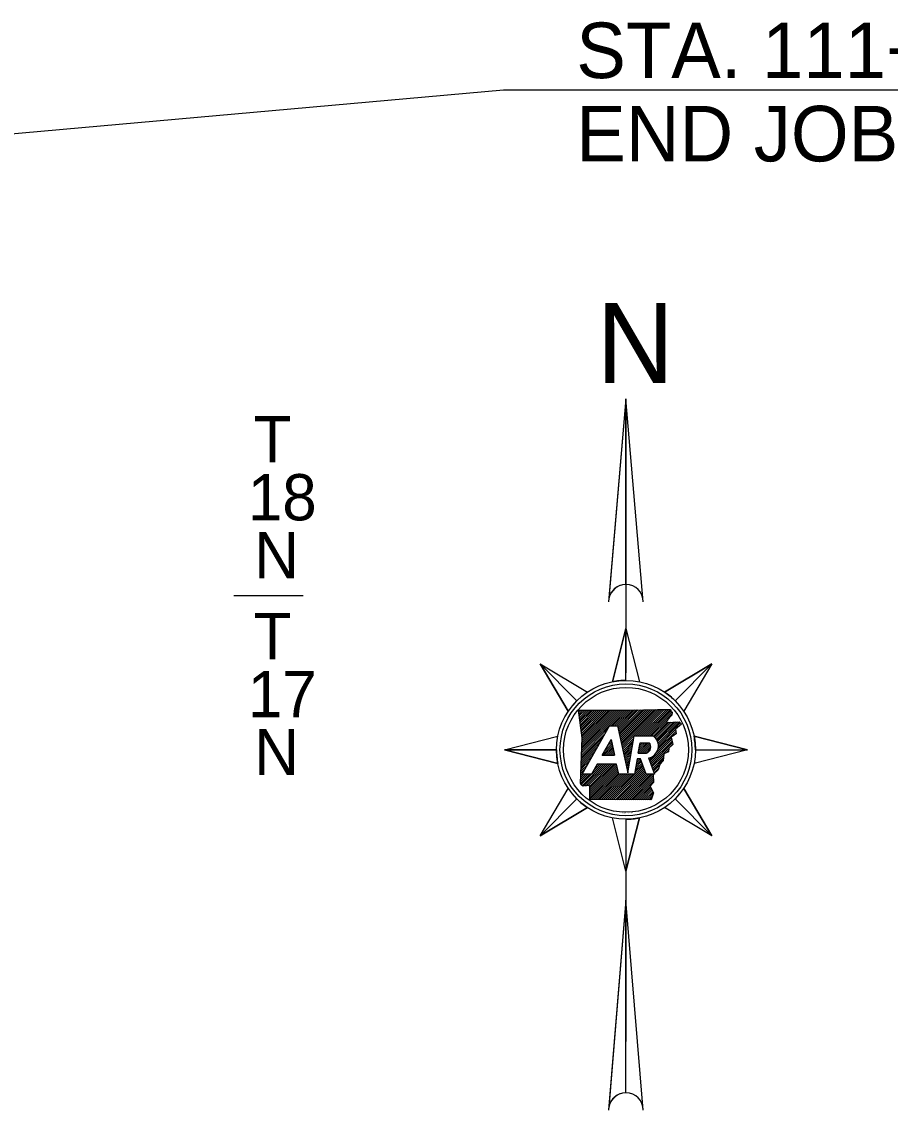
# Model space of a CAD drawing. Extents: x 166 to 3406, y 71 to 2074.
# Drawn here: x 2315.6 to 2690.8, y 490.1 to 960.6 of the extents above; entities that cross this region are included whole.
import ezdxf

# ---------------------------------------------------------------- set-up
doc = ezdxf.new("R2010")
doc.units = 0
for name, color, linetype in [('2', 7, 'Continuous'), ('Default', 7, 'Continuous'), ('Level 6', 7, 'Continuous'), ('R_Draft', 7, 'Continuous')]:
    doc.layers.add(name, color=color, linetype=linetype)

msp = doc.modelspace()

# ---------------------------------------------------------------- linework, layer by layer
at = {"layer": 'Default'}
msp.add_line((2826.89, 931.07), (2523.75, 931.07), dxfattribs=at)
msp.add_lwpolyline([(2523.75, 931.07), (1751.41, 862.02), (1897.01, 884.67), (1902.22, 875.51)], dxfattribs=at)
at = {"layer": 'Level 6'}
msp.add_line((2407.22, 712.51), (2437.22, 712.51), dxfattribs=at)
at = {"layer": 'R_Draft'}
for p, q in [((2576.6, 797.56), (2569.21, 711.09)), ((2576.6, 797.56), (2576.6, 679.13)), ((2576.6, 717.31), (2576.6, 797.56)), ((2569.31, 712.29), (2569.65, 712.63)), ((2569.35, 712.76), (2570.03, 713.44)), ((2576.6, 698.35), (2570.76, 675.28)), ((2576.6, 675.85), (2576.6, 698.35)), ((2539.48, 682.98), (2555.39, 667.07)), ((2555.39, 667.07), (2539.48, 682.98)), ((2539.48, 682.98), (2551.66, 662.53)), ((2613.72, 682.98), (2593.27, 670.79)), ((2597.81, 667.07), (2613.72, 682.98)), ((2597.81, 667.07), (2613.72, 682.98)), ((2556.15, 662.76), (2556.41, 663.03)), ((2556.24, 662.01), (2557.26, 663.03)), ((2556.34, 661.25), (2558.11, 663.03)), ((2556.43, 660.5), (2558.96, 663.03)), ((2556.53, 659.74), (2559.81, 663.03)), ((2556.62, 658.99), (2560.65, 663.02)), ((2556.71, 658.24), (2561.5, 663.02)), ((2556.81, 657.48), (2562.35, 663.02)), ((2556.9, 656.73), (2563.2, 663.02)), ((2557, 655.97), (2564.05, 663.02)), ((2557.09, 655.22), (2564.89, 663.02)), ((2557.18, 654.46), (2565.74, 663.02)), ((2557.28, 653.71), (2566.59, 663.02)), ((2557.37, 652.95), (2567.44, 663.02)), ((2557.4, 644.5), (2575.94, 663.04)), ((2557.43, 645.37), (2575.09, 663.04)), ((2557.46, 646.25), (2574.24, 663.03)), ((2557.47, 652.2), (2568.29, 663.02)), ((2557.49, 647.13), (2573.39, 663.03)), ((2557.52, 648.01), (2572.54, 663.03)), ((2557.55, 648.88), (2571.69, 663.03)), ((2557.56, 651.44), (2569.14, 663.02)), ((2557.57, 649.76), (2570.84, 663.03)), ((2557.6, 650.64), (2569.99, 663.03)), ((2570, 656.25), (2576.79, 663.04)), ((2570.85, 656.25), (2577.64, 663.04)), ((2571.7, 656.25), (2578.5, 663.05)), ((2572.55, 656.25), (2579.36, 663.06)), ((2573.07, 655.93), (2580.22, 663.08)), ((2573.22, 655.23), (2581.08, 663.09)), ((2573.37, 654.53), (2581.94, 663.1)), ((2573.52, 653.83), (2582.81, 663.12)), ((2573.67, 653.13), (2583.67, 663.13)), ((2573.82, 652.43), (2584.53, 663.14)), ((2573.97, 651.74), (2585.39, 663.16)), ((2574.12, 651.04), (2586.25, 663.17)), ((2574.27, 650.34), (2587.12, 663.18)), ((2574.42, 649.64), (2587.98, 663.2)), ((2574.57, 648.94), (2588.84, 663.21)), ((2574.72, 648.24), (2589.7, 663.22)), ((2574.87, 647.54), (2590.57, 663.24)), ((2575.02, 646.84), (2591.44, 663.26)), ((2580.91, 651.89), (2592.3, 663.28)), ((2581.76, 651.89), (2593.17, 663.3)), ((2582.61, 651.89), (2594.04, 663.32)), ((2583.46, 651.89), (2594.91, 663.34)), ((2584.31, 651.89), (2595.78, 663.36)), ((2585.16, 651.89), (2595.97, 662.7)), ((2586, 651.89), (2596.38, 662.26)), ((2586.85, 651.89), (2596.49, 661.52)), ((2587.7, 651.89), (2594.55, 658.74)), ((2557.37, 643.62), (2568.82, 655.07)), ((2557.65, 635.35), (2569.49, 656.25)), ((2569.49, 656.25), (2573.01, 656.25)), ((2588.47, 651.81), (2594.38, 657.72)), ((2588.94, 651.43), (2595.28, 657.77)), ((2589.35, 650.99), (2596.17, 657.81)), ((2589.72, 650.51), (2597.07, 657.86)), ((2590.03, 649.98), (2597.96, 657.91)), ((2590.29, 649.39), (2598.86, 657.95)), ((2590.49, 648.73), (2599.66, 657.91)), ((2590.6, 648), (2600.06, 657.46)), ((2590.61, 647.16), (2598.03, 654.58)), ((2599.68, 656.23), (2600.45, 657)), ((2557.31, 641.86), (2566.61, 651.16)), ((2557.34, 642.74), (2567.71, 653.11)), ((2566.36, 643.55), (2570.23, 650.39)), ((2568.52, 647.37), (2570.46, 649.31)), ((2569.63, 649.32), (2570.31, 650.01)), ((2575.17, 646.14), (2579.98, 650.96)), ((2575.32, 645.44), (2579.8, 649.93)), ((2580.15, 651.89), (2588.37, 651.89)), ((2586.93, 640.93), (2596.33, 650.34)), ((2587.15, 640.31), (2596.49, 649.65)), ((2589.69, 644.54), (2596.17, 651.03)), ((2590.43, 646.13), (2598.13, 653.83)), ((2597.18, 652.03), (2598.23, 653.08)), ((2629.1, 645.85), (2606.02, 651.7)), ((2524.1, 645.85), (2546.6, 645.85)), ((2546.6, 645.85), (2524.1, 645.85)), ((2524.1, 645.85), (2547.17, 640.01)), ((2557.23, 639.23), (2563.28, 645.29)), ((2557.25, 640.11), (2564.39, 647.24)), ((2557.28, 640.99), (2565.5, 649.2)), ((2566.4, 643.55), (2570.76, 647.91)), ((2567.25, 643.55), (2570.91, 647.21)), ((2567.41, 645.41), (2570.61, 648.61)), ((2568.1, 643.55), (2571.06, 646.51)), ((2568.95, 643.55), (2571.21, 645.81)), ((2569.79, 643.55), (2571.36, 645.11)), ((2575.47, 644.75), (2579.63, 648.9)), ((2575.62, 644.05), (2579.45, 647.88)), ((2575.77, 643.35), (2579.27, 646.85)), ((2575.92, 642.65), (2579.09, 645.82)), ((2576.07, 641.95), (2578.91, 644.79)), ((2581.93, 644.47), (2586.4, 648.94)), ((2582.11, 645.5), (2585.55, 648.94)), ((2582.29, 646.52), (2584.7, 648.94)), ((2582.47, 647.55), (2583.85, 648.94)), ((2582.65, 648.58), (2583, 648.94)), ((2582.71, 648.94), (2586.57, 648.94)), ((2582.78, 644.47), (2586.87, 648.56)), ((2583.63, 644.47), (2587.16, 648)), ((2584.48, 644.47), (2587.31, 647.31)), ((2585.33, 644.47), (2587.24, 646.39)), ((2587.38, 639.69), (2596.65, 648.96)), ((2587.61, 639.07), (2596.81, 648.27)), ((2593.91, 644.52), (2595.1, 645.71)), ((2606.6, 645.85), (2629.1, 645.85)), ((2606.6, 645.85), (2629.1, 645.85)), ((2557.17, 637.48), (2561.07, 641.38)), ((2557.2, 638.35), (2562.17, 643.33)), ((2566.36, 643.55), (2571.69, 643.55)), ((2570.64, 643.55), (2571.51, 644.42)), ((2571.49, 643.55), (2571.66, 643.72)), ((2576.22, 641.25), (2578.73, 643.77)), ((2576.37, 640.55), (2578.55, 642.74)), ((2576.51, 639.85), (2578.37, 641.71)), ((2576.66, 639.15), (2578.19, 640.68)), ((2580.66, 637.21), (2583.6, 640.15)), ((2580.84, 638.24), (2583.37, 640.77)), ((2581.02, 639.27), (2583.14, 641.39)), ((2581.2, 640.3), (2582.9, 641.99)), ((2581.38, 641.32), (2582.05, 641.99)), ((2582.92, 641.99), (2581.5, 641.99)), ((2581.93, 644.47), (2585.46, 644.47)), ((2585.38, 635.35), (2582.92, 641.99)), ((2586.4, 642.35), (2588.99, 635.35)), ((2586.47, 642.17), (2586.73, 642.43)), ((2586.7, 641.55), (2588.31, 643.16)), ((2587.84, 638.45), (2592.93, 643.54)), ((2588.07, 637.83), (2592.84, 642.6)), ((2588.3, 637.21), (2592.74, 641.65)), ((2556.98, 631.35), (2560.98, 635.35)), ((2556.99, 632.21), (2560.13, 635.35)), ((2557.02, 633.09), (2559.28, 635.35)), ((2557.05, 633.97), (2558.43, 635.35)), ((2557.08, 634.84), (2557.74, 635.51)), ((2557.11, 635.72), (2558.85, 637.46)), ((2557.14, 636.6), (2559.96, 639.42)), ((2557.29, 630.81), (2566.21, 639.73)), ((2561.71, 635.35), (2557.65, 635.35)), ((2557.8, 630.47), (2567.06, 639.73)), ((2558.41, 630.23), (2567.91, 639.73)), ((2559.41, 630.39), (2568.76, 639.73)), ((2560.28, 630.4), (2569.6, 639.73)), ((2560.94, 630.22), (2570.45, 639.73)), ((2560.97, 628.55), (2572.15, 639.73)), ((2560.97, 629.4), (2571.3, 639.73)), ((2560.97, 627.71), (2572.6, 639.33)), ((2560.98, 626.86), (2572.75, 638.63)), ((2560.98, 626.01), (2572.9, 637.93)), ((2560.98, 625.17), (2573.05, 637.23)), ((2560.99, 624.33), (2573.2, 636.53)), ((2564.2, 639.73), (2561.71, 635.35)), ((2561.84, 624.33), (2573.35, 635.83)), ((2562.68, 637.04), (2565.36, 639.73)), ((2562.69, 624.33), (2573.7, 635.35)), ((2563.54, 624.33), (2574.55, 635.35)), ((2563.78, 639), (2564.51, 639.73)), ((2572.51, 639.73), (2564.2, 639.73)), ((2564.38, 624.33), (2575.4, 635.35)), ((2565.23, 624.33), (2576.25, 635.35)), ((2566.08, 624.32), (2577.1, 635.35)), ((2566.92, 624.32), (2577.95, 635.35)), ((2567.77, 624.32), (2578.8, 635.35)), ((2568.62, 624.32), (2579.64, 635.35)), ((2569.47, 624.32), (2584.06, 638.91)), ((2570.31, 624.32), (2584.29, 638.29)), ((2571.16, 624.32), (2584.52, 637.67)), ((2572.01, 624.31), (2584.75, 637.05)), ((2572.85, 624.31), (2584.98, 636.43)), ((2580.34, 635.35), (2573.45, 635.35)), ((2573.7, 624.31), (2585.2, 635.81)), ((2574.55, 624.31), (2585.58, 635.35)), ((2575.4, 624.31), (2586.43, 635.35)), ((2576.24, 624.31), (2587.28, 635.35)), ((2576.81, 638.46), (2578.01, 639.65)), ((2576.96, 637.76), (2577.83, 638.63)), ((2577.09, 624.31), (2588.13, 635.35)), ((2577.11, 637.06), (2577.66, 637.6)), ((2577.26, 636.36), (2577.48, 636.57)), ((2580.49, 636.19), (2583.83, 639.53)), ((2588.99, 635.35), (2585.38, 635.35)), ((2588.53, 636.59), (2591.13, 639.19)), ((2588.76, 635.97), (2590.77, 637.98)), ((2577.94, 624.3), (2588.41, 634.78)), ((2578.78, 624.3), (2588.45, 633.97)), ((2579.63, 624.3), (2588.49, 633.16)), ((2580.48, 624.3), (2588.53, 632.35)), ((2581.33, 624.3), (2587.13, 630.11)), ((2582.17, 624.3), (2587.4, 629.52)), ((2583.02, 624.3), (2587.66, 628.93)), ((2583.87, 624.29), (2587.92, 628.35)), ((2584.71, 624.29), (2588.18, 627.76)), ((2585.56, 624.29), (2588.4, 627.13)), ((2586.41, 624.29), (2588.02, 625.9)), ((2613.72, 608.73), (2601.54, 629.18)), ((2539.48, 608.73), (2555.39, 624.64)), ((2555.39, 624.64), (2539.48, 608.73)), ((2587.26, 624.29), (2587.63, 624.67)), ((2597.81, 624.64), (2613.72, 608.73)), ((2597.81, 624.64), (2613.72, 608.73)), ((2539.48, 608.73), (2559.92, 620.92)), ((2576.6, 593.35), (2582.44, 616.43)), ((2576.6, 615.85), (2576.6, 615.86)), ((2576.6, 615.85), (2576.6, 519.82)), ((2576.6, 615.85), (2576.6, 593.35)), ((2576.6, 580.81), (2569.2, 491.3)), ((2576.6, 497.56), (2576.6, 580.81))]:
    msp.add_line(p, q, dxfattribs=at)
for points in [[(2584.1, 709.81), (2576.6, 797.56), (2569.1, 709.81)], [(2570.76, 675.28), (2576.6, 698.35), (2582.44, 675.28)], [(2551.66, 662.53), (2539.48, 682.98), (2559.92, 670.79)], [(2593.27, 670.79), (2613.72, 682.98), (2601.54, 662.53)], [(2556.12, 663.03), (2567.82, 663.02), (2578.1, 663.04), (2590.22, 663.23), (2595.83, 663.36)], [(2556.96, 631.35), (2557.62, 651), (2556.12, 663.03)], [(2573.01, 656.25), (2577.36, 635.9), (2580.15, 651.89)], [(2599.51, 657.98), (2600.52, 656.92), (2598, 654.85), (2598.27, 652.75), (2596.11, 651.32), (2596.85, 648.1), (2595.18, 646.58), (2595.03, 644.92), (2593, 644.19), (2592.68, 641.07), (2591.22, 639.5), (2590.52, 637.15), (2588.39, 635.21), (2588.55, 631.78), (2587.11, 630.16), (2588.43, 627.21), (2587.51, 624.29)], [(2594.1, 657.71), (2599.59, 657.99)], [(2547.17, 640.01), (2524.1, 645.85), (2547.17, 651.7)], [(2570.23, 650.39), (2571.69, 643.55)], [(2606.02, 651.7), (2629.1, 645.85), (2606.02, 640.01)], [(2581.93, 644.47), (2582.71, 648.94)], [(2581.5, 641.99), (2580.34, 635.35)], [(2573.45, 635.35), (2572.51, 639.73)], [(2559.92, 620.92), (2539.48, 608.73), (2551.66, 629.18)], [(2587.51, 624.29), (2560.98, 624.33), (2560.97, 630.19)], [(2601.54, 629.18), (2613.72, 608.73), (2593.27, 620.92)], [(2582.44, 616.43), (2576.6, 593.35), (2570.76, 616.43)], [(2584.1, 490.06), (2576.6, 580.81), (2569.1, 490.06)]]:
    msp.add_lwpolyline(points, dxfattribs=at)
for radius in [30, 28.5, 27]:
    msp.add_circle((2576.6, 645.85), radius, dxfattribs=at)
for centre, radius, start, end in [((2576.6, 709.81), 7.5, 0, 180), ((2576.6, 709.81), 7.5, 90, 170.2296), ((2576.6, 645.85), 30, 90, 101.2291), ((2576.6, 645.85), 30, 45, 56.2291), ((2576.6, 645.85), 30, 135, 146.2291), ((2585.31, 647.55), 5.31, 281.8626, 54.8705), ((2576.6, 645.85), 30, 0, 11.2291), ((2576.6, 645.85), 30, 180, 191.2291), ((2584.61, 647.06), 2.72, 288.1268, 43.8902), ((2576.6, 645.85), 30, 315, 326.2291), ((2576.6, 645.85), 30, 225, 236.2291), ((2576.6, 645.85), 30, 270, 281.2291), ((2576.6, 490.06), 7.5, 0, 180), ((2576.6, 490.06), 7.5, 90, 170.5511)]:
    msp.add_arc(centre, radius, start, end, dxfattribs=at)
for points in [[(2595.83, 663.36), (2595.87, 663.04), (2595.97, 662.88), (2595.99, 662.57), (2596.11, 662.44), (2596.32, 662.31), (2596.51, 662.1), (2596.55, 661.85), (2596.49, 661.6), (2596.48, 661.32), (2596.45, 661.07), (2596.4, 660.85), (2596.23, 660.67), (2596.06, 660.54), (2595.91, 660.39), (2595.8, 660.23), (2595.62, 660.05), (2595.43, 659.87), (2595.28, 659.71), (2595.12, 659.51), (2595.05, 659.28), (2594.88, 659.13), (2594.75, 658.98), (2594.58, 658.79), (2594.49, 658.59), (2594.33, 658.37), (2594.29, 658.15), (2594.18, 657.97), (2594.18, 657.95)], [(2560.97, 630.19), (2561, 630.17), (2560.86, 630.27), (2560.67, 630.36), (2560.46, 630.38), (2560.19, 630.41), (2559.97, 630.44), (2559.74, 630.59), (2559.49, 630.43), (2559.22, 630.31), (2559.06, 630.44), (2558.85, 630.36), (2558.7, 630.4), (2558.45, 630.23), (2558.21, 630.29), (2558.04, 630.24), (2557.82, 630.25), (2557.77, 630.49), (2557.56, 630.53), (2557.38, 630.63), (2557.26, 630.88), (2557.17, 631.08), (2556.96, 631.35)]]:
    msp.add_spline(points, degree=3, dxfattribs=at)

# ---------------------------------------------------------------- texts
at = {"layer": '2'}
for s, p in [('STA. 111+25.00', (2555.14, 936.22)), ('END JOB 101053', (2555.14, 900.22))]:
    msp.add_text(s, height=24, dxfattribs=at).set_placement(p)
at = {"layer": 'Default'}
for s, p in [('T', (2415.69, 770.09)), ('18', (2413.25, 745.05)), ('N', (2416, 720.01)), ('T', (2415.69, 685.01)), ('17', (2413.25, 659.97)), ('N', (2416, 634.93))]:
    msp.add_text(s, height=20, dxfattribs=at).set_placement(p)
at = {"layer": 'R_Draft'}
for s, height, p in [('N', 34.62, (2563.95, 804.37)), ('DWB 7-27-17', 0.5833, (2574.76, 618.35))]:
    msp.add_text(s, height=height, dxfattribs=at).set_placement(p)

doc.saveas('drawing.dxf')
